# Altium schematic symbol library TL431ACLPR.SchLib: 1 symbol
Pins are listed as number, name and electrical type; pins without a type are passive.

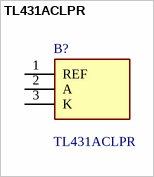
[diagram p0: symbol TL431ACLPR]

## TL431ACLPR
designator B?
1% Accuracy Adjustable Precision Shunt Regulator; Manufacturer_Name: Texas Instruments; Geometry.Height: 5.34mm
footprint TL431ACLPR
pins: 1 REF, 2 A, 3 K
